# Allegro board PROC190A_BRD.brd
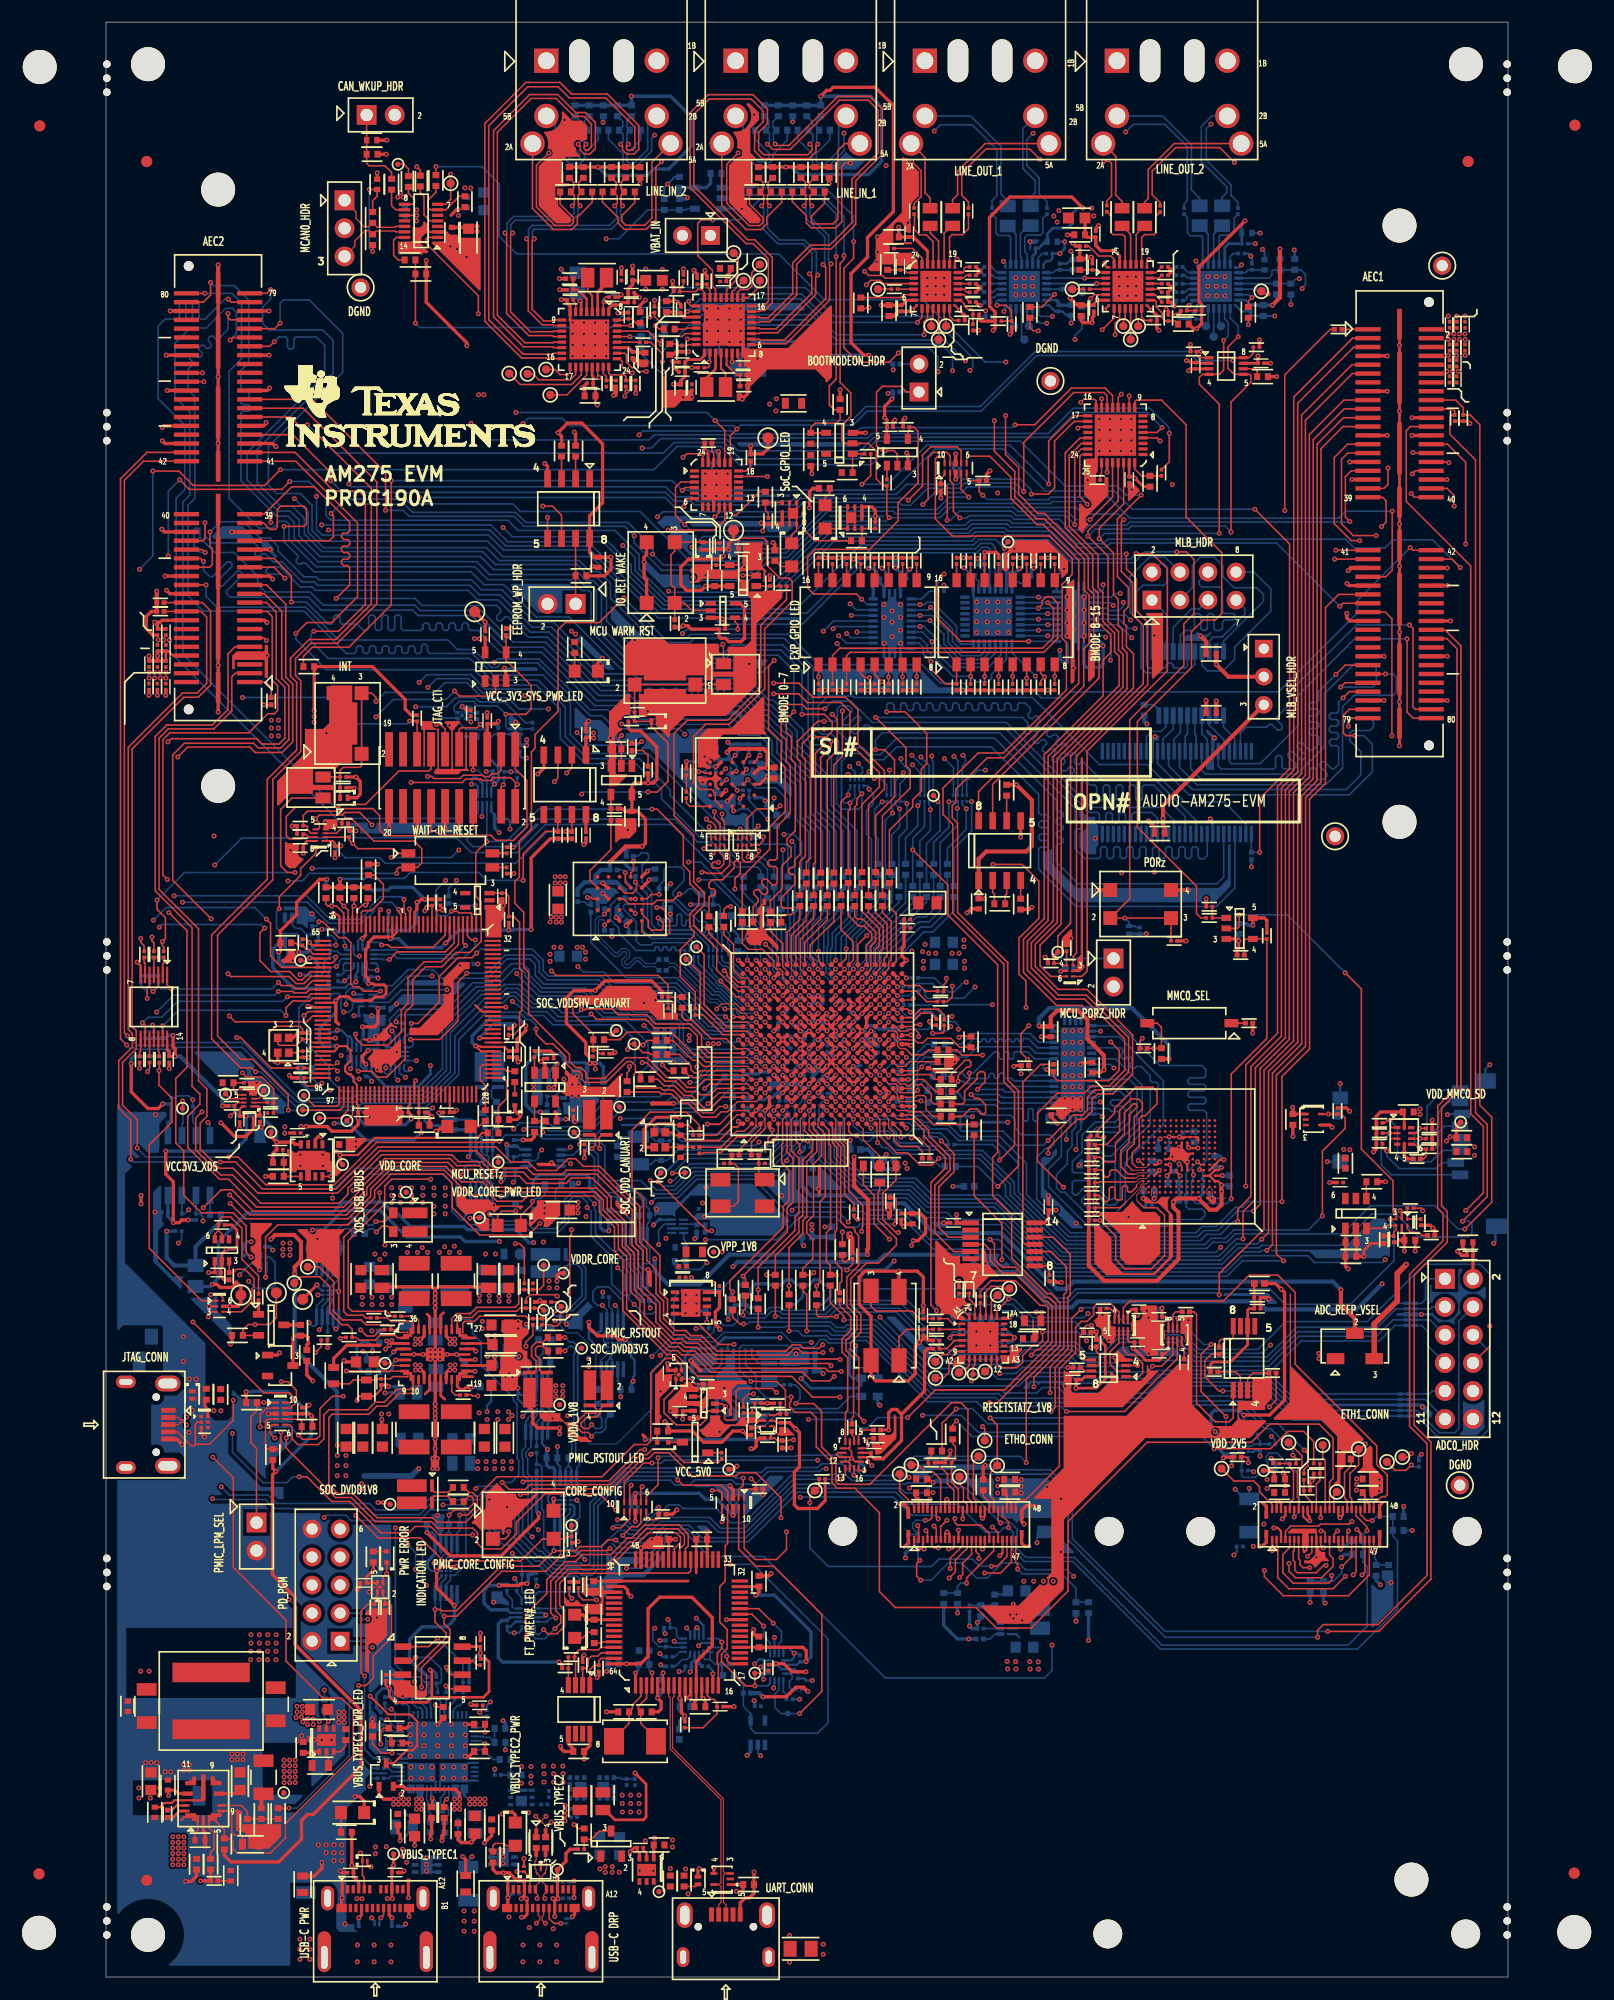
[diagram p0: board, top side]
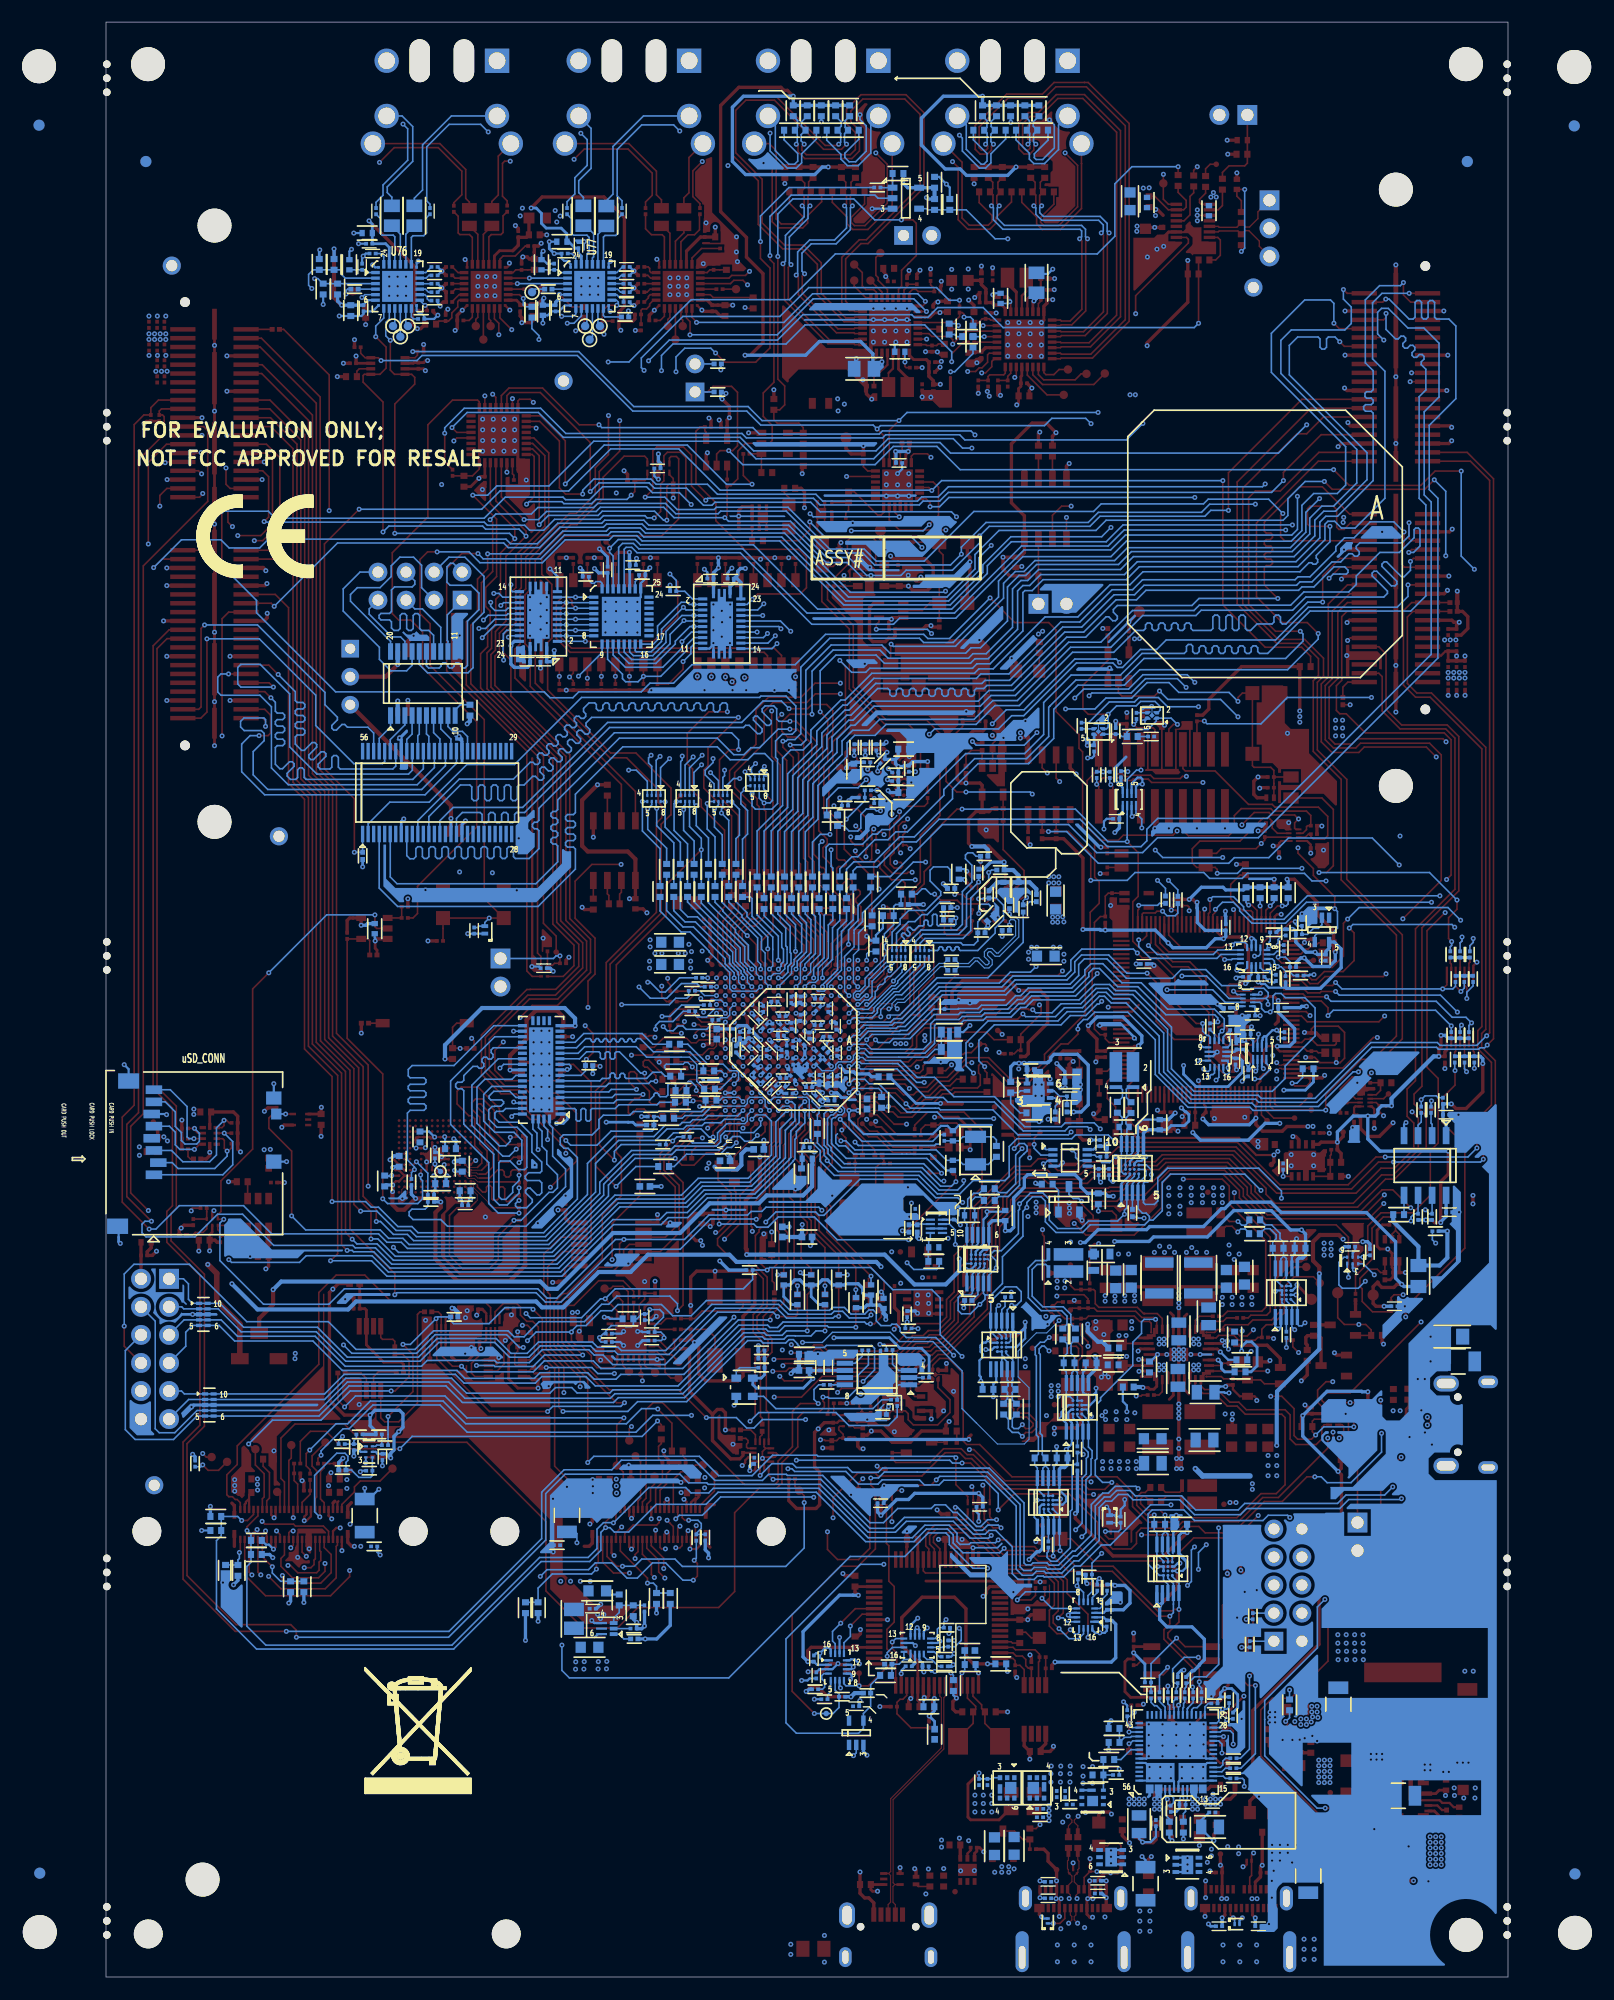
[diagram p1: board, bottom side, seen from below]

Outline 127 x 177 mm; copper layers: TOP, L02_GND1, L03_SIG1, L04_PWR1, L05_GND2, BOTTOM. Coordinates in mm from the lower left corner of the outline.
Outline path: 0,177 0,0 127,0 127,177 0,177

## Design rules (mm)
constraint set DEFAULT: min track width 0.147
net group AEC1_GPIO0_1: nets AEC1_GPIO0_1 N28268314
net group AUDIO_EXT_REFCLK0: nets AUDIO_EXT_REFCLK0 N29649892
net group AUDIO_EXT_REFCLK1: nets AUDIO_EXT_REFCLK1 AUDIO_EXT_REFCLK1__R
net group AUDIO_EXT_REFCLK2: nets AUDIO_EXT_REFCLK2 AUDIO_EXT_REFCLK2_R
net group CAN_DP1: nets MCAN0_CAN_H MCAN0_CAN_L
net group CDCE_CLKOUT_1: nets CDCE_CLKOUT_1 N27176072
net group CPSW_RGMII1_TD0: nets CPSW_RGMII1_TD0 N28084397
net group CPSW_RGMII1_TD1: nets CPSW_RGMII1_TD1 N28084399
net group CPSW_RGMII1_TD2: nets CPSW_RGMII1_TD2 N28084409
net group CPSW_RGMII1_TD3: nets CPSW_RGMII1_TD3 N28084411
net group CPSW_RGMII1_TXC: nets CPSW_RGMII1_TXC CPSW_RGMII_TXC_R
net group CPSW_RGMII2_TD0: nets CPSW_RGMII2_TD0 N28084427
net group CPSW_RGMII2_TD2: nets CPSW_RGMII2_TD2 N28084431
net group CPSW_RGMII2_TD3: nets CPSW_RGMII2_TD3 N28084433
net group CPSW_RGMII2_TXC: nets CPSW_RGMII2_TXC CPSW_RGMII2_TXC_R
net group DP1_USB_SOC: nets SOC_USB0_DM SOC_USB0_DP
net group DP_CONN2: nets USBC_CONN2_DM USBC_CONN2_DP
net group DP_XDS_USB: nets XDS_USB_DM XDS_USB_DP
net group DVDD3V3: nets DVDD3V3_N DVDD3V3_P
net group HYPERBUS0_CK: nets HYPERBUS0_CK N28088261
net group HYPERBUS0_CK#: nets HYPERBUS0_CK# N28088302
net group HYPERBUS0_CS#: nets HYPERBUS0_CS# N28088339
net group HYPERBUS0_DQ0: nets HYPERBUS0_DQ0 SOC_HYPERBUS0_DQ0
net group HYPERBUS0_DQ1: nets HYPERBUS0_DQ1 SOC_HYPERBUS0_DQ1
net group HYPERBUS0_DQ2: nets HYPERBUS0_DQ2 SOC_HYPERBUS0_DQ2
net group HYPERBUS0_DQ3: nets HYPERBUS0_DQ3 SOC_HYPERBUS0_DQ3
net group HYPERBUS0_DQ4: nets HYPERBUS0_DQ4 SOC_HYPERBUS0_DQ4
net group HYPERBUS0_DQ5: nets HYPERBUS0_DQ5 SOC_HYPERBUS0_DQ5
net group HYPERBUS0_DQ6: nets HYPERBUS0_DQ6 SOC_HYPERBUS0_DQ6
net group HYPERBUS0_DQ7: nets HYPERBUS0_DQ7 SOC_HYPERBUS0_DQ7
net group HYPERBUS0_RWDS: nets HYPERBUS0_RWDS N27995683
net group MCASP0_ACLKR: nets MCASP0_ACLKR MCASP0_ACLKR_R
net group MCASP0_ACLKX: nets MCASP0_ACLKX N29650058
net group MCASP0_AFSR: nets MCASP0_AFSR MCASP0_AFSR_R
net group MCASP0_AFSX: nets MCASP0_AFSX MCASP0_AFSX_R
net group MCASP0_AXR0: nets MCASP0_AXR0 MCASP0_AXR0_R
net group MCASP0_AXR1: nets MCASP0_AXR1 MCASP0_AXR1_R
net group MCASP0_AXR2: nets MCASP0_AXR2 MCASP0_AXR2_R
net group MCASP0_AXR3: nets MCASP0_AXR3 MCASP0_AXR3_R
net group MCASP0_AXR4: nets MCASP0_AXR4 MCASP0_AXR4_R
net group MCASP0_AXR5: nets MCASP0_AXR5 MCASP0_AXR5_R
net group MCASP0_AXR6_R: nets MCASP0_AXR6_R UART2_RXD_FET
net group MCASP0_AXR7: nets MCASP0_AXR7 MCASP0_AXR7_R
net group MCASP0_AXR8_R: nets MCASP0_AXR8_R OBSCLK0
net group MCASP0_AXR9: nets MCASP0_AXR9 MCASP0_AXR9_R
net group MCASP1_ACLKR_R: nets MCASP1_ACLKR_R PCM6240_MCASP1_ACLKR
net group MCASP1_ACLKX_R: nets MCASP1_ACLKX_R TAD5212_MCASP1_ACLKX
net group MCASP1_AFSR_R: nets MCASP1_AFSR_R PCM6240_MCASP1_AFSR
net group MCASP1_AFSX_R: nets MCASP1_AFSX_R TAD5212_MCASP1_AFSX
net group MCASP1_AXR0_R: nets MCASP1_AXR0_R PCM6240_MCASP1_AXR0
net group MCASP1_AXR2_R: nets MCASP1_AXR2_R PCM6240_MCASP1_AXR2
net group MCASP2_ACLKR: nets MCASP2_ACLKR MCASP2_ACLKR_R
net group MCASP2_ACLKX: nets MCASP2_ACLKX MCASP2_ACLKX_R
net group MCASP2_AFSR: nets MCASP2_AFSR MCASP2_AFSR_R
net group MCASP2_AFSX: nets MCASP2_AFSX MCASP2_AFSX_R
net group MCASP2_AXR0: nets MCASP2_AXR0 MCASP2_AXR0_R
net group MCASP2_AXR1: nets MCASP2_AXR1 MCASP2_AXR1_R
net group MCASP2_AXR2: nets MCASP2_AXR2 MCASP2_AXR2_R
net group MCASP2_AXR3: nets MCASP2_AXR3 MCASP2_AXR3_R
net group MCASP2_AXR4: nets MCASP2_AXR4 MCASP2_AXR4_R
net group MCASP2_AXR5: nets MCASP2_AXR5 MCASP2_AXR5_R
net group MCASP3_ACLKX: nets MCASP3_ACLKX N29649623
net group MCASP3_AFSX: nets MCASP3_AFSX N29649611
net group MCASP3_AXR0: nets MCASP3_AXR0 N29649563
net group MCASP3_AXR1: nets MCASP3_AXR1 N29649575
net group MCASP3_AXR2: nets MCASP3_AXR2 N29649587
net group MCASP3_AXR3: nets MCASP3_AXR3 N29649599
net group MCASP4_ACLKR_R: nets MCASP4_ACLKR_FET MCASP4_ACLKR_R
net group MCASP4_AFSR_R: nets MCASP4_AFSR_FET MCASP4_AFSR_R
net group MCASP4_AXR0_R: nets MCASP4_AXR0_FET MCASP4_AXR0_R
net group MCASP4_AXR3_R: nets MCASP4_AXR3_FET MCASP4_AXR3_R
net group MCASP4_AXR4_R: nets MCASP4_AXR4_FET MCASP4_AXR4_R
net group MCASP4_AXR5_R: nets MCASP4_AXR5_FET MCASP4_AXR5_R
net group OSC1_XI: nets N27975321 OSC1_XI
net group OSC1_XO: nets N27975317 OSC1_XO
net group OSPI_CLK: nets OSPI_CLK SOC_OSPI_CLK
net group OSPI_DQS: nets OSPI_DQS OSPI_DQS_SOC
net group PCMPCM1_IN1: nets PCM1_IN1N PCM1_IN1P
net group PCMPCM1_IN2: nets PCM1_IN2N PCM1_IN2P
net group PCMPCM1_IN3: nets PCM1_IN3N PCM1_IN3P
net group PCMPCM1_IN4: nets PCM1_IN4N PCM1_IN4P
net group PCMPCM2_IN1: nets PCM2_IN1N PCM2_IN1P
net group PCMPCM2_IN2: nets PCM2_IN2N PCM2_IN2P
net group PCMPCM2_IN3: nets PCM2_IN3N PCM2_IN3P
net group PCMPCM2_IN4: nets PCM2_IN4N PCM2_IN4P
net group RESET_STATZ: nets RESET_STATZ RESETSTATZ_1V8
net group SEC_REF_N: nets N27175817 SEC_REF_N
net group SEC_REF_P: nets N27175821 SEC_REF_P
net group SOC_DVDD1V8: nets SOC_DVDD1V8_N SOC_DVDD1V8_P
net group SOC_DVDD3V3: nets SOC_DVDD3V3_N SOC_DVDD3V3_P
net group SOC_MMC0_CLK: nets MMC0_CLK SOC_MMC0_CLK
net group SOC_MMC0_CMD_R: nets SOC_MMC0_CMD SOC_MMC0_CMD_R
net group SOC_MMC0_DAT0_R: nets SOC_MMC0_DAT0 SOC_MMC0_DAT0_R
net group SOC_MMC0_DAT1_R: nets SOC_MMC0_DAT1 SOC_MMC0_DAT1_R
net group SOC_MMC0_DAT2_R: nets SOC_MMC0_DAT2 SOC_MMC0_DAT2_R
net group SOC_MMC0_DAT3_R: nets SOC_MMC0_DAT3 SOC_MMC0_DAT3_R
net group SOC_MMC0_DAT4_R: nets SOC_MMC0_DAT4 SOC_MMC0_DAT4_R
net group SOC_MMC0_DAT5_R: nets SOC_MMC0_DAT5 SOC_MMC0_DAT5_R
net group SOC_MMC0_DAT6_R: nets SOC_MMC0_DAT6 SOC_MMC0_DAT6_R
net group SOC_MMC0_DAT7_R: nets SOC_MMC0_DAT7 SOC_MMC0_DAT7_R
net group SOC_OSPI_DQ0: nets OSPI_DQ0 SOC_OSPI_DQ0
net group SOC_OSPI_DQ1: nets OSPI_DQ1 SOC_OSPI_DQ1
net group SOC_OSPI_DQ2: nets OSPI_DQ2 SOC_OSPI_DQ2
net group SOC_OSPI_DQ3: nets OSPI_DQ3 SOC_OSPI_DQ3
net group SOC_OSPI_DQ4: nets OSPI_DQ4 SOC_OSPI_DQ4
net group SOC_OSPI_DQ5: nets OSPI_DQ5 SOC_OSPI_DQ5
net group SOC_OSPI_DQ6: nets OSPI_DQ6 SOC_OSPI_DQ6
net group SOC_OSPI_DQ7: nets OSPI_DQ7 SOC_OSPI_DQ7
net group SOC_VDD_CANUART: nets SOC_VDD_CANUART_N SOC_VDD_CANUART_P
net group SOC_VDDSHV_CANUART: nets SOC_VDDSHV_CANUART_N SOC_VDDSHV_CANUART_P
net group VDD_0V85: nets VDD_0V85_N VDD_0V85_P
net group VDD_1V8: nets VDD_1V8_N VDD_1V8_P
net group VDD_CANUART: nets VDD_CANUART_N VDD_CANUART_P
net group VDD_CORE: nets VDD_CORE_N VDD_CORE_P
net group VDDA_1V8: nets VDDA_1V8_N VDDA_1V8_P
net group VDDR_CORE: nets VDDR_CORE_N VDDR_CORE_P
net group VDDSHV_CANUART: nets VDDSHV_CANUART_N VDDSHV_CANUART_P
net group WKUP_LFOSCO_XO: nets N27972730 WKUP_LFOSCO_XO
net group CPSW_RGMII2_TD1: nets N28084429
net group EMMC_MG: nets EMMC_CLK EMMC_CMD EMMC_D0 EMMC_D1 EMMC_D2 EMMC_D3 EMMC_D4 EMMC_D5 EMMC_D6 EMMC_D7
net group MCASP1_AXR1_R: nets MCASP1_AXR1_R TAD5212_1_DIN TAD5212_2_DIN TAD5212_3_DIN TAD5212_4_DIN TAD5212_MCASP1_AXR1
net group MCASP3_ACLKR: nets MCASP3_ACLKR MCASP4_ACLKX_FET MCASP4_ACLKX_R
net group MCASP3_AFSR: nets MCASP3_AFSR MCASP4_AFSX_FET MCASP4_AFSX_R
net group OSPI0_CSN0: nets N29295413 N29295438 OSPI0_CSN0 OSPI_CS
net group PWR: nets LDO_3V3 N24307354 N24307356 SOC_DVDD3V3_FB1 SOC_VDD_CANUART SOC_VDDSHV5_SDIO SOC_VDDSHV_CANUART VCC1V8_SYS_N VCC_0V85 VCC_1V8_FT4232 VCC_3V3_AVDD VCC_3V3_FT4232 VCC_CORE VCC_CORE_N VDDA_1V8_FB3 VDDA_1V8_FB_OSC VDDA_ADC0 VDDR_CANUART VDDSHV_SDIO VPHY_3V3_FT4232 VPLL_3V3_FT4232 VPP_1V8
net group RGMII1_RD: nets CPSW_RGMII1_RD0 CPSW_RGMII1_RD1 CPSW_RGMII1_RD2 CPSW_RGMII1_RD3 CPSW_RGMII1_RX_DV CPSW_RGMII1_RXC
net group RGMII2_RD: nets CPSW_RGMII2_RD0 CPSW_RGMII2_RD1 CPSW_RGMII2_RD2 CPSW_RGMII2_RD3 CPSW_RGMII2_RX_DV CPSW_RGMII2_RXC
net group RGMII2_TD: nets CPSW_RGMII2_TX_EN
net group RGMII_TD: nets CPSW_RGMII1_TX_EN

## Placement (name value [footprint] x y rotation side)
C1  0.022uF  [CAP0402_0-75]  24.07 166.31 0 top
C2  0.1uF  [CAP0402_0-75]  48.36 163.39 270 top
C3  0.1uF  [CAP0402_0-75]  65.51 163.39 270 top
C11  22uF  [CAP0402_1]  41.63 161.63 0 top
C12  22uF  [CAP0402_1]  43.55 161.63 180 top
C13  22uF  [CAP0402_1]  45.47 161.63 0 top
C14  22uF  [CAP0402_1]  47.42 161.63 180 top
C15  22uF  [CAP0402_1]  58.77 161.63 0 top
C16  22uF  [CAP0402_1]  60.72 161.63 180 top
C17  22uF  [CAP0402_1]  62.66 161.63 0 top
C18  22uF  [CAP0402_1]  64.61 161.63 180 top
C20  1uF  [CAP0201_0-5]  90.66 160.11 270 top
C21  1uF  [CAP0201_0-5]  95.49 160.1 270 top
C22  1uF  [CAP0201_0-5]  73.2 159.88 270 top
C23  1uF  [CAP0201_0-5]  78.13 159.88 270 top
C24  47uF  [CAP0805_1-5]  74.65 159.34 270 top
C25  47uF  [CAP0805_1-5]  76.68 159.34 270 top
C26  47uF  [CAP0805_1-5]  92.05 159.34 270 top
C27  47uF  [CAP0805_1-5]  94.08 159.34 270 top
C28  0.1uF  [CAP0402_0-75]  112.76 65.24 0 top
C29  0.1uF  [CAP0201_0-5]  72.76 157.82 90 top
C30  0.1uF  [CAP0201_0-5]  89.65 157.79 90 top
C31  10uF  [CAP0402_0-75]  88.2 157.74 180 top
C32  10uF  [CAP0402_0-75]  71.32 157.55 180 top
C33  4.7uF  [CAP0402_0-75]  112.77 66.5 180 top
C35  1uF  [CAP0201_0-5]  88.48 156.72 180 top
C37  0.1uF  [CAP0402_0-75]  118.1 66.71 0 top
C38  1uF  [CAP0201_0-5]  71.09 156.5 180 top
C42  10uF  [CAP0402_0-75]  70.8 155.06 90 top
C43  10uF  [CAP0402_0-75]  88.2 155.06 90 top
C45  0.1uF  [CAP0201_0-5]  71.96 154.85 90 top
C46  0.1uF  [CAP0201_0-5]  89.35 154.85 90 top
C47  0.1uF  [CAP0201_0-5]  78.52 154.83 0 top
C48  0.1uF  [CAP0201_0-5]  95.92 154.83 0 top
C49  0.1uF  [CAP0402_0-75]  56.1 154.7 0 top
C50  0.1uF  [CAP0201_0-5]  78.52 154.07 0 top
C51  0.1uF  [CAP0201_0-5]  95.92 154.07 0 top
C52  2.2uF  [CAP0201_0-75]  47.7 153.95 90 top
C53  0.1uF  [CAP0201_0-5]  46.69 153.89 270 top
C54  2.2uF  [CAP0201_0-75]  41.98 153.77 180 top
C55  1uF  [CAP0201_0-5]  55.91 153.52 0 top
C56  0.1uF  [CAP0201_0-5]  78.52 153.31 0 top
C57  0.1uF  [CAP0201_0-5]  95.92 153.31 0 top
C60  0.1uF  [CAP0201_0-5]  42.04 152.76 0 top
C61  0.1uF  [CAP0201_0-5]  78.52 152.55 0 top
C62  0.1uF  [CAP0201_0-5]  95.92 152.55 0 top
C63  1uF  [CAP0201_0-5]  47.58 152.5 0 top
C64  0.1uF  [CAP0201_0-5]  45.85 152.11 0 top
C65  1uF  [CAP0201_0-5]  42.04 151.87 180 top
C66  1uF  [CAP0201_0-5]  78.52 151.66 0 top
C67  1uF  [CAP0201_0-5]  95.92 151.66 0 top
C68  0.1uF  [CAP0201_0-5]  47.58 151.61 0 top
C69  1uF  [CAP0201_0-5]  111.78 71.93 180 top
C70  220pF  [CAP0402_0-75]  114.66 72 0 top
C71  10uF  [CAP0402_0-75]  50.77 151.24 90 top
C72  0.1uF  [CAP0201_0-5]  72.08 151.09 270 top
C73  0.1uF  [CAP0201_0-5]  89.48 151.09 270 top
C74  0.1uF  [CAP0201_0-5]  52.07 150.95 90 top
C75  10uF  [CAP0402_0-75]  70.93 150.88 270 top
C76  10uF  [CAP0402_0-75]  88.33 150.88 270 top
C77  10uF  [CAP0402_0-75]  48.38 150.25 90 top
C78  0.1uF  [CAP0201_0-5]  47.33 150.42 90 top
C81  0.1uF  [CAP0201_0-5]  52.18 147.44 270 top
C82  10uF  [CAP0402_0-75]  51.06 147.38 270 top
C84  0.1uF  [CAP0201_0-5]  47.69 146.86 270 top
C85  10uF  [CAP0402_0-75]  48.83 146.58 270 top
C86  0.1uF  [CAP0201_0-5]  52.18 146.21 180 top
C87  1uF  [CAP0201_0-5]  57.71 145.95 0 top
C88  2.2uF  [CAP0402_0-75]  122.82 74.73 180 top
C89  0.1uF  [CAP0201_0-5]  53.91 145.71 180 top
C90  1uF  [CAP0201_0-5]  52.18 145.32 180 top
C92  0.1uF  [CAP0201_0-5]  57.71 145.06 180 top
C93  0.1uF  [CAP0402_0-75]  122.81 75.99 180 top
C95  1uF  [CAP0201_0-5]  43.85 144.3 180 top
C96  2.2uF  [CAP0201_0-75]  57.77 144.05 0 top
C97  0.1uF  [CAP0201_0-5]  53.07 143.93 90 top
C98  2.2uF  [CAP0201_0-75]  52.05 143.87 270 top
C99  0.1uF  [CAP0201_0-5]  104.63 146.11 0 top
C100  0.1uF  [CAP0402_0-75]  43.85 143.16 180 top
C101  0.1uF  [CAP0201_0-5]  98.71 145.89 90 top
C102  0.1uF  [CAP0402_0-75]  107.51 77.64 90 top
C103  0.1uF  [CAP0402_0-75]  117.96 78.32 180 top
C104  12pF  [CAP0201_0-5]  74.03 58.36 90 top
C105  12pF  [CAP0201_0-5]  74.04 59.89 90 top
C107  4700pF  [CAP0402_0-75]  24.56 162.31 90 top
C109  0.1uF  [CAP0402_0-75]  63.84 137.3 270 top
C121  10uF  [CAP0402_0-75]  83.55 57.8 0 top
C122  0.01uF  [CAP0201_0-5]  55.16 137.08 0 bottom
C126  0.01uF  [CAP0201_0-5]  92.68 135.56 90 top
C128  0.1uF  [CAP0201_0-5]  121.71 149.59 90 top
C129  0.1uF  [CAP0201_0-5]  122.37 149.59 90 top
C130  1uF  [CAP0201_0-5]  123.11 149.59 90 top
C133  0.1uF  [CAP0201_0-5]  121.7 147.53 270 top
C134  1uF  [CAP0201_0-5]  122.36 147.53 270 top
C135  1uF  [CAP0201_0-5]  123.1 147.53 270 top
C136  0.1uF  [CAP0201_0-5]  71.02 140.33 0 top
C137  0.1uF  [CAP0201_0-5]  121.7 146.1 90 top
C138  1uF  [CAP0201_0-5]  122.36 146.1 90 top
C140  0.1uF  [CAP0201_0-5]  43.47 112.51 90 top
C141  0.1uF  [CAP0201_0-5]  121.7 144.65 270 top
C142  1uF  [CAP0201_0-5]  122.36 144.65 270 top
C146  0.1uF  [CAP0402_0-75]  102.66 94.92 270 bottom
C147  0.1uF  [CAP0201_0-5]  43.47 103.38 270 top
C148  0.1uF  [CAP0402_0-75]  55.14 126.42 90 top
C149  4.7uF  [CAP0402_0-75]  60.53 109.02 90 top
C150  0.1uF  [CAP0201_0-5]  93.57 60.45 180 top
C151  0.1uF  [CAP0201_0-5]  93.45 57.48 180 top
C160  1uF  [CAP0201_0-5]  4.66 121.77 90 top
C161  0.1uF  [CAP0201_0-5]  5.42 121.77 90 top
C164  0.1uF  [CAP0201_0-5]  76.77 68.28 180 top
C165  0.1uF  [CAP0201_0-5]  85.37 69.72 270 top
C167  1uF  [CAP0201_0-5]  4.66 120.32 270 top
C168  0.1uF  [CAP0201_0-5]  5.42 120.32 270 top
C169  0.1uF  [CAP0201_0-5]  34.53 113.75 90 top
C170  1uF  [CAP0201_0-5]  3.9 118.89 90 top
C171  1uF  [CAP0201_0-5]  4.66 118.89 90 top
C172  0.1uF  [CAP0201_0-5]  5.42 118.89 90 top
C174  1uF  [CAP0201_0-5]  3.89 116.83 270 top
C175  0.1uF  [CAP0201_0-5]  4.65 116.83 270 top
C176  0.1uF  [CAP0201_0-5]  5.42 116.83 270 top
C182  100pF  [CAP0201_0-5]  67.64 65.29 270 top
C188  100pF  [CAP0201_0-5]  77.65 77.9 180 bottom
C190  0.01uF  [CAP0201_0-5]  35.87 97.85 270 top
C192  0.1uF  [CAP0201_0-5]  5.72 83.08 270 top
C197  1uF  [CAP0201_0-5]  40.27 83.16 180 top
C201  10uF  [CAP0402_1]  35.76 55.42 0 bottom
C202  10uF  [CAP0402_0-75]  73.04 68.65 270 top
C203  0.1uF  [CAP0201_0-5]  17.8 93.68 270 top
C205  18pF  [CAP0402_0-75]  52.05 76.68 90 top
C207  1uF  [CAP0201_0-5]  42.34 78.21 270 top
C208  0.01uF  [CAP0201_0-5]  32.99 91.72 180 bottom
C209  18pF  [CAP0402_0-75]  52.05 74.67 90 top
C213  18pF  [CAP0402_0-75]  50.29 76.16 270 bottom
C215  0.1uF  [CAP0201_0-5]  36.48 85.59 270 top
C216  18pF  [CAP0402_0-75]  50.29 73.48 90 bottom
C217  12pF  [CAP0201_0-5]  17.81 85.2 270 top
C221  0.01uF  [CAP0201_0-5]  36.48 83.56 270 top
C222  1uF  [CAP0201_0-5]  37.24 83.56 270 top
C223  12pF  [CAP0201_0-5]  17.81 83.54 90 top
C224  1uF  [CAP0201_0-5]  61.57 81.23 270 bottom
C225  0.1uF  [CAP0201_0-5]  17.65 81.41 0 top
C226  22uF  [CAP0603_1]  23.08 63.2 270 top
C227  47uF  [CAP0805_1-5]  24.99 63.2 270 top
C228  47uF  [CAP0805_1-5]  34.65 63.2 270 top
C229  22uF  [CAP0603_1]  36.48 63.2 270 top
C231  0.1uF  [CAP0201_0-5]  23.12 78.29 180 top
C232  0.01uF  [CAP0201_0-5]  27.11 78.29 180 top
C233  1uF  [CAP0201_0-5]  28.61 78.29 0 top
C234  0.01uF  [CAP0201_0-5]  30.85 78.29 180 top
C235  0.1uF  [CAP0201_0-5]  12.12 77.67 90 top
C236  0.1uF  [CAP0201_0-5]  13.94 77.72 90 top
C240  2.2uF  [CAP0402_0-75]  28.82 77.12 0 top
C241  1uF  [CAP0201_0-5]  17.34 76.42 180 top
C242  2.2uF  [CAP0603_1]  35.72 59.03 0 top
C243  15pF  [CAP0201_0-5]  15.74 74.9 0 top
C244  2.2uF  [CAP0402_0-75]  21.62 75.38 0 top
C245  100pF  [CAP0201_0-5]  50.92 87.42 270 top
C246  2.2uF  [CAP0603_1]  35.72 55.37 0 top
C247  2.2uF  [CAP0201_0-75]  52.24 64.34 180 top
C248  100pF  [CAP0201_0-5]  45.31 83.6 0 top
C249  2.2uF  [CAP0603_1]  23.46 55.69 180 top
C250  4.7uF  [CAP0402_0-75]  9.08 52.76 90 top
C251  0.1uF  [CAP0201_0-5]  52.22 63.35 180 top
C254  2.2uF  [CAP0603_1]  35.72 53.57 0 top
C255  1uF  [CAP0201_0-5]  55.57 62.28 90 top
C256  2.2uF  [CAP0603_1]  23.26 48.82 90 top
C257  22uF  [CAP0603_1]  25.04 48.82 90 top
C258  22uF  [CAP0603_1]  34.27 48.82 90 top
C259  2.2uF  [CAP0603_1]  32.18 48.74 180 bottom
C260  0.1uF  [CAP0603_1]  36.14 48.81 90 top
C261  0.1uF  [CAP0603_1]  21.75 48.82 90 top
C262  0.1uF  [CAP0402_0-75]  42.83 20.42 0 top
C263  4.7uF  [CAP0402_0-75]  44.17 35.34 270 top
C264  0.1uF  [CAP0402_0-75]  44.23 32.84 270 top
C265  1uF  [CAP0201_0-5]  67.63 56.74 0 bottom
C266  0.1uF  [CAP0201_0-5]  67.63 55.98 180 bottom
C267  0.1uF  [CAP0402_0-75]  10.39 52.74 90 top
C269  18pF  [CAP0402_0-75]  46.89 24 180 top
C270  18pF  [CAP0402_0-75]  48.94 24 0 top
C271  10uF  [CAP0402_0-75]  114.31 45.09 0 top
C272  10uF  [CAP0402_0-75]  73.88 45.09 0 top
C273  10uF  [CAP0402_0-75]  106.31 45.09 0 top
C274  10uF  [CAP0402_0-75]  81.86 45.06 0 top
C275  0.1uF  [CAP0402_0-75]  50.48 39.63 0 top
C276  0.1uF  [CAP0402_0-75]  106.31 43.88 0 top
C277  0.1uF  [CAP0402_0-75]  114.32 43.87 0 top
C278  0.1uF  [CAP0402_0-75]  73.88 43.84 0 top
C279  0.1uF  [CAP0402_0-75]  81.88 43.9 0 top
C280  0.1uF  [CAP0402_0-75]  53.8 24.47 180 top
C281  0.1uF  [CAP0402_0-75]  53.96 39.63 180 top
C282  0.1uF  [CAP0201_0-5]  55.63 24.48 180 top
C283  0.01uF  [CAP0201_0-5]  48.4 11.71 0 top
C284  0.1uF  [CAP0201_0-5]  61.57 55.2 270 bottom
C285  2.2uF  [CAP0402_0-75]  50.11 11.95 0 top
C286  1uF  [CAP0201_0-5]  62.33 55.2 270 bottom
C287  10uF  [CAP0402_0-75]  51.12 8.69 270 top
C288  0.1uF  [CAP0402_0-75]  59.15 30.34 270 top
C289  0.1uF  [CAP0402_0-75]  59.15 35.84 270 top
C290  10uF  [CAP0402_0-75]  63.74 56.38 180 bottom
C291  0.1uF  [CAP0402_0-75]  52.37 8.69 270 top
C292  0.1uF  [CAP0201_0-5]  33.91 30.19 90 top
C293  0.1uF  [CAP0201_0-5]  61.12 49.91 270 top
C295  0.1uF  [CAP0402_0-75]  58.21 8.37 0 top
C300  0.01uF  [CAP0201_0-5]  23.3 35.68 0 top
C301  0.01uF  [CAP0201_0-5]  33.85 24.6 180 top
C302  10uF  [CAP0603_1]  19.29 24.21 0 top
C303  4.7uF  [CAP0402_0-75]  30.54 23.95 270 top
C305  220pF  [CAP0402_0-75]  33.84 22.88 180 top
C306  220pF  [CAP0402_0-75]  26.1 22.53 0 top
C307  220pF  [CAP0402_0-75]  24.14 22.28 90 top
C308  330pF  [CAP0402_0-75]  21.71 21.94 90 top
C309  4.7uF  [CAP0402_0-75]  26.37 21.18 0 top
C310  1uF  [CAP0402_0-75]  17.86 20.79 90 top
C312  220pF  [CAP0402_0-75]  33.84 20.42 180 top
C317  47uF  [CAP0805_1-5]  42.93 15.92 270 top
C318  47uF  [CAP0805_1-5]  45.01 15.91 270 top
C319  10uF  [CAP0402_0-75]  29.48 14.9 90 top
C320  10uF  [CAP0402_0-75]  30.63 14.9 90 top
C321  0.1uF  [CAP0402_0-75]  26.43 14.26 270 top
C322  10uF  [CAP0603_1]  33.42 13.78 270 top
C323  0.1uF  [CAP0402_0-75]  34.94 13.78 270 top
C324  10uF  [CAP0603_1]  27.96 13.54 270 top
C325  0.1uF  [CAP0402_0-75]  31.89 13.43 270 top
C326  0.01uF  [CAP0201_0-5]  26.17 9.46 0 top
C327  0.01uF  [CAP0201_0-5]  22.14 9.45 180 top
C329  0.1uF  [CAP0402_0-75]  62.2 168.97 270 bottom
C330  0.1uF  [CAP0402_0-75]  45.06 168.97 270 bottom
C331  22uF  [CAP0402_1]  65.09 167.21 180 bottom
C332  22uF  [CAP0402_1]  63.14 167.21 0 bottom
C333  22uF  [CAP0402_1]  61.22 167.21 180 bottom
C334  22uF  [CAP0402_1]  59.3 167.21 0 bottom
C335  22uF  [CAP0402_1]  47.94 167.21 180 bottom
C336  22uF  [CAP0402_1]  46 167.21 0 bottom
C337  22uF  [CAP0402_1]  44.08 167.21 180 bottom
C338  22uF  [CAP0402_1]  42.16 167.21 0 bottom
C340  0.1uF  [CAP0402_0-75]  51.94 162.5 90 bottom
C341  1uF  [CAP0201_0-5]  102.54 159.88 270 bottom
C342  1uF  [CAP0201_0-5]  97.65 159.88 270 bottom
C343  1uF  [CAP0201_0-5]  85.24 159.88 270 bottom
C344  1uF  [CAP0201_0-5]  80.26 159.88 270 bottom
C345  47uF  [CAP0805_1-5#2]  101.1 159.47 270 bottom
C346  47uF  [CAP0805_1-5#2]  99.07 159.47 270 bottom
C347  47uF  [CAP0805_1-5#2]  83.76 159.47 270 bottom
C348  47uF  [CAP0805_1-5#2]  81.68 159.44 270 bottom
C349  10uF  [CAP0402_0-75]  103.34 157.9 0 bottom
C350  10uF  [CAP0402_0-75]  85.7 157.12 0 bottom
C351  0.1uF  [CAP0201_0-5]  103.16 156.93 0 bottom
C352  0.1uF  [CAP0201_0-5]  84.2 156.8 90 bottom
C353  1uF  [CAP0201_0-5]  102.85 156.04 0 bottom
C354  1uF  [CAP0201_0-5]  85.45 156.04 0 bottom
C355  10uF  [CAP0402_0-75]  104.95 155.03 90 bottom
C356  10uF  [CAP0402_0-75]  87.55 155.03 90 bottom
C357  0.1uF  [CAP0201_0-5]  103.8 154.85 90 bottom
C358  0.1uF  [CAP0201_0-5]  86.4 154.85 90 bottom
C359  0.1uF  [CAP0201_0-5]  97.24 154.83 180 bottom
C360  0.1uF  [CAP0201_0-5]  79.84 154.83 180 bottom
C361  0.1uF  [CAP0201_0-5]  97.24 154.07 180 bottom
C362  0.1uF  [CAP0201_0-5]  79.84 154.07 180 bottom
C363  1uF  [CAP0805_1-5#2]  42.71 153.4 90 bottom
C364  0.1uF  [CAP0201_0-5]  97.24 153.31 180 bottom
C365  0.1uF  [CAP0201_0-5]  79.84 153.31 180 bottom
C366  0.1uF  [CAP0201_0-5]  97.24 152.55 180 bottom
C367  0.1uF  [CAP0201_0-5]  79.84 152.55 180 bottom
C368  10uF  [CAP0402_0-75]  45.96 151.99 90 bottom
C369  1uF  [CAP0201_0-5]  97.24 151.78 180 bottom
C370  1uF  [CAP0201_0-5]  79.84 151.66 180 bottom
C371  0.1uF  [CAP0201_0-5]  103.67 151.09 270 bottom
C372  0.1uF  [CAP0201_0-5]  86.27 151.09 270 bottom
C373  10uF  [CAP0402_0-75]  104.82 150.88 270 bottom
C374  10uF  [CAP0402_0-75]  87.43 150.91 270 bottom
C378  10uF  [CAP0402_0-75]  55.09 147.15 0 bottom
C379  1uF  [CAP0805_1-5#2]  58.33 145.61 0 bottom
C382  0.1uF  [CAP0201_0-5]  77.58 58.39 0 bottom
C383  0.1uF  [CAP0201_0-5]  77.58 57.63 0 bottom
C384  0.1uF  [CAP0201_0-5]  78.21 59.75 270 bottom
C385  10uF  [CAP0402_0-75]  79.72 59.59 0 bottom
C386  0.1uF  [CAP0201_0-5]  81.46 58.25 180 bottom
C387  0.1uF  [CAP0201_0-5]  81.46 57.49 180 bottom
C388  0.1uF  [CAP0402_0-75]  54.75 111.17 180 bottom
C389  0.1uF  [CAP0402_0-75]  59.26 109.36 270 bottom
C390  0.1uF  [CAP0402_0-75]  54.74 107.24 180 bottom
C391  0.1uF  [CAP0201_0-5]  79.28 127.84 0 bottom
C393  0.1uF  [CAP0201_0-5]  81.56 127.41 270 bottom
C394  0.1uF  [CAP0201_0-5]  72.25 126.61 180 bottom
C395  0.1uF  [CAP0201_0-5]  70.41 126.61 0 bottom
C408  0.1uF  [CAP0201_0-5]  88.86 119.09 0 bottom
C409  0.1uF  [CAP0201_0-5]  87.36 119.09 180 bottom
C414  0.1uF  [CAP0201_0-5]  14.12 66.12 180 bottom
C415  0.01uF  [CAP0201_0-5]  33.05 114.43 270 top
C416  0.01uF  [CAP0201_0-5]  37.49 111.24 90 bottom
C417  8.2pF  [CAP0201_0-5]  32.33 112.31 180 bottom
C421  0.1uF  [CAP0201_0-5]  87.35 91.34 180 bottom
C427  0.1uF  [CAP0402_0-75]  47.11 53.21 180 bottom
C428  0.1uF  [CAP0402_0-75]  45.11 53.21 0 bottom
C429  1uF  [CAP0201_0-5]  66.53 80.5 315 bottom
C430  0.1uF  [CAP0201_0-5]  25.57 95.04 270 bottom
C432  1uF  [CAP0201_0-5]  62.5 88.58 180 bottom
C434  1uF  [CAP0201_0-5]  61.57 87.67 90 bottom
C437  1uF  [CAP0201_0-5]  63.31 80.57 180 bottom
C440  1uF  [CAP0201_0-5]  60.86 86.06 270 bottom
C441  0.22uF  [CAP0201_0-5]  63.32 82.87 315 bottom
C443  1uF  [CAP0201_0-5]  68.13 82.76 315 bottom
C445  0.22uF  [CAP0201_0-5]  68.11 81.23 225 bottom
C446  1uF  [CAP0201_0-5]  69.57 85.29 270 bottom
C447  0.1uF  [CAP0201_0-5]  62.53 86.17 180 bottom
C448  0.22uF  [CAP0201_0-5]  62.5 87.66 135 bottom
C449  22pF  [CAP0201_0-5]  62.49 82.82 315 bottom
C451  1uF  [CAP0201_0-5]  62.52 79.6 225 bottom
C453  1uF  [CAP0201_0-5]  64.1 88.49 90 bottom
C454  1uF  [CAP0201_0-5]  65.65 81.39 180 bottom
C455  0.1uF  [CAP0201_0-5]  16.5 92.3 90 bottom
C460  0.22uF  [CAP0201_0-5]  65.73 86.07 225 bottom
C461  1uF  [CAP0201_0-5]  64.92 88.47 90 bottom
C462  0.22uF  [CAP0201_0-5]  63.31 85.23 90 bottom
C463  1uF  [CAP0201_0-5]  66.62 86.03 90 bottom
C465  0.1uF  [CAP0201_0-5]  68.12 86.87 45 bottom
C466  0.1uF  [CAP0201_0-5]  64.75 84.46 90 bottom
C467  1uF  [CAP0201_0-5]  67.32 86.09 135 bottom
C468  0.22uF  [CAP0201_0-5]  64.9 86.12 270 bottom
C469  0.1uF  [CAP0201_0-5]  23.72 90.55 180 bottom
C470  0.1uF  [CAP0201_0-5]  22.35 90.55 0 bottom
C471  1uF  [CAP0201_0-5]  68.76 85.29 270 bottom
C473  0.1uF  [CAP0201_0-5]  5.33 69.25 0 bottom
C477  0.22uF  [CAP0201_0-5]  68.12 82.09 135 bottom
C478  0.1uF  [CAP0201_0-5]  36.94 75.5 270 bottom
C483  1uF  [CAP0201_0-5]  72.03 68.86 270 top
C484  1uF  [CAP0201_0-5]  60.77 83.68 90 bottom
C485  1uF  [CAP0201_0-5]  63.97 84.61 45 bottom
C488  1uF  [CAP0201_0-5]  20.54 87.76 180 bottom
C489  0.1uF  [CAP0201_0-5]  21.49 108.65 180 top
C490  0.1uF  [CAP0201_0-5]  66.46 88.32 180 bottom
C493  0.1uF  [CAP0201_0-5]  67.16 83.66 270 bottom
C494  0.22uF  [CAP0201_0-5]  65.72 86.98 0 bottom
C495  1uF  [CAP0201_0-5]  72.57 95.76 180 top
C497  4.7uF  [CAP0201_0-5]  72.57 95 180 top
C498  0.1uF  [CAP0402_0-75]  98.56 76.06 90 bottom
C500  0.1uF  [CAP0201_0-5]  25.47 87.76 180 bottom
C501  1uF  [CAP0201_0-5]  64.1 82.86 315 bottom
C502  1uF  [CAP0201_0-5]  61.84 83.88 45 bottom
C503  0.1uF  [CAP0402_0-75]  100.45 73.85 90 bottom
C504  2.2uF  [CAP0402_0-75]  95.79 75 0 bottom
C505  0.1uF  [CAP0201_0-5]  67.31 82.04 315 bottom
C506  1uF  [CAP0201_0-5]  65.65 80.41 315 bottom
C508  1uF  [CAP0201_0-5]  61.29 79.35 0 bottom
C509  1uF  [CAP0201_0-5]  60.79 81.26 270 bottom
C511  0.1uF  [CAP0201_0-5]  23.18 87.04 180 bottom
C512  1uF  [CAP0201_0-5]  61.7 82.84 45 bottom
C514  0.1uF  [CAP0402_0-75]  94.73 73.41 270 bottom
C515  0.1uF  [CAP0201_0-5]  23.59 85.35 180 bottom
C516  0.1uF  [CAP0201_0-5]  20.24 85.27 270 bottom
C517  1uF  [CAP0201_0-5]  62.38 80.46 90 bottom
C518  2.2uF  [CAP0402_0-75]  101.75 72.07 90 bottom
C520  0.1uF  [CAP0402_0-75]  96.69 71.83 0 bottom
C521  0.1uF  [CAP0402_0-75]  94.47 71.19 180 bottom
C524  0.1uF  [CAP0402_0-75]  20.83 65.98 180 bottom
C525  0.1uF  [CAP0402_0-75]  18.83 65.98 0 bottom
C527  1uF  [CAP0201_0-5]  94.46 69.86 180 bottom
C528  0.1uF  [CAP0201_0-5]  23.54 81.82 90 bottom
C529  0.1uF  [CAP0201_0-5]  5.61 78.07 0 bottom
C532  0.1uF  [CAP0603_1]  23.88 63.5 270 bottom
C533  100uF  [CAP1210_2-75]  31.58 63.29 270 bottom
C534  100uF  [CAP1210_2-75]  28.05 63.29 270 bottom
C535  2.2uF  [CAP0603_1]  34.12 63.21 270 bottom
C536  2.2uF  [CAP0603_1]  25.51 63.21 270 bottom
C537  0.1uF  [CAP0603_1]  35.53 63.16 270 bottom
C538  0.1uF  [CAP0201_0-5]  10.29 60.73 180 bottom
C546  10uF  [CAP0805_1-5]  27.12 59.82 90 bottom
C547  10uF  [CAP0805_1-5]  29.82 58.45 270 bottom
C555  0.47uF  [CAP0402_0-75]  34.4 53.42 0 bottom
C559  0.1uF  [CAP0402_0-75]  39.76 55.6 180 bottom
C560  0.1uF  [CAP0402_0-75]  37.76 55.6 0 bottom
C561  4.7uF  [CAP0402_0-75]  32.47 55.23 90 bottom
C565  10uF  [CAP0805_1-5]  29.9 54.25 90 bottom
C572  10uF  [CAP0805_1-5]  27.39 52.94 180 bottom
C574  0.1uF  [CAP0201_0-5]  36.35 33.53 270 bottom
C575  0.1uF  [CAP0201_0-5]  36.35 32 90 bottom
C576  0.47uF  [CAP0402_0-75]  24.77 57.94 90 bottom
C592  47uF  [CAP0805_1-5]  32.17 46.51 180 bottom
C593  47uF  [CAP0805_1-5]  27.49 48.62 0 bottom
C597  0.1uF  [CAP0402_0-75]  42.39 46.99 180 bottom
C598  0.1uF  [CAP0402_0-75]  40.39 46.99 0 bottom
C599  0.1uF  [CAP0402_0-75]  45.95 28.35 0 bottom
C602  0.1uF  [CAP0201_0-5]  101.96 47.09 270 bottom
C603  0.1uF  [CAP0402_0-75]  31.56 40.98 180 bottom
C604  0.1uF  [CAP0402_0-75]  29.56 40.98 0 bottom
C605  1000pF  [CAP1206_1-75]  4.51 55.74 180 bottom
C606  0.1uF  [CAP0402_0-75]  48.72 28.29 0 bottom
C607  0.1uF  [CAP0402_0-75]  52.46 24.47 180 bottom
C608  0.1uF  [CAP0201_0-5]  52.76 28.14 0 bottom
C609  0.1uF  [CAP0201_0-5]  48.16 114.54 180 top
C610  1000pF  [CAP1206_1-75]  85.24 41.8 90 bottom
C611  1000pF  [CAP1206_1-75]  103.56 41.78 90 bottom
C612  0.1uF  [CAP0201_0-5]  54.28 28.14 180 bottom
C613  0.1uF  [CAP0201_0-5]  35.09 41.41 270 bottom
C614  22uF  [CAP0603_1]  82.49 34.96 180 bottom
C615  120pF  [CAP0201_0-5]  78.22 33.37 90 bottom
C616  0.1uF  [CAP0201_0-5]  82.91 33.35 180 bottom
C617  0.1uF  [CAP0201_0-5]  62.66 27.31 90 bottom
C618  0.1uF  [CAP0201_0-5]  62.87 28.83 270 bottom
C620  4.7uF  [CAP0603_1]  83.2 29.85 0 bottom
C622  0.1uF  [CAP0201_0-5]  93.65 94.74 90 bottom
C631  4.7uF  [CAP0402_0-75]  35.68 21.24 0 bottom
C638  0.1uF  [CAP0201_0-5]  47.16 17.65 90 bottom
C639  0.1uF  [CAP0201_0-5]  40.88 16.56 270 bottom
C640  1uF  [CAP0201_0-5]  42.38 15.23 180 bottom
C641  0.01uF  [CAP0201_0-5]  26.78 14.9 0 bottom
C642  0.01uF  [CAP0201_0-5]  31.9 13.93 270 bottom
C643  4.7uF  [CAP0805_1-5]  26.99 13.58 0 bottom
C644  4.7uF  [CAP0805_1-5]  33.42 13.83 270 bottom
C646  10uF  [CAP0603_1]  44.74 11.87 270 bottom
C647  10uF  [CAP0603_1]  46.52 11.84 270 bottom
C648  1000pF  [CAP1206_1-75]  18.1 9.13 90 bottom
C649  0.01uF  [CAP0201_0-5]  37.16 8.72 180 bottom
C650  0.01uF  [CAP0201_0-5]  41.67 8.61 0 bottom
C651  1000pF  [CAP1206_1-75]  32.83 8.45 90 bottom
C652  0.01uF  [CAP0201_0-5]  37.15 7.56 180 bottom
C653  0.01uF  [CAP0201_0-5]  41.66 7.12 0 bottom
C654  0.01uF  [CAP0201_0-5]  26.17 4.59 0 bottom
C655  0.01uF  [CAP0201_0-5]  22.61 4.59 180 bottom
C657  0.22uF  [CAP0201_0-5]  64.09 86.85 90 bottom
C658  0.22uF  [CAP0201_0-5]  65.34 84.05 90 bottom
C659  0.22uF  [CAP0201_0-5]  62.5 83.64 225 bottom
C660  1uF  [CAP0201_0-5]  64.91 82.18 180 bottom
C662  1uF  [CAP0201_0-5]  67.46 87.65 90 bottom
C663  1uF  [CAP0201_0-5]  65.88 85.24 180 bottom
C787  0.1uF  [CAP0402_0-75]  89.33 82.35 90 top
C3494  0.1uF  [CAP0402_0-75]  4.42 14.91 90 top
C3497  0.1uF  [CAP0402_0-75]  1.98 24.51 270 top
C3625  10uF  [CAP1206_2]  14.27 18.08 90 top
C3627  10uF  [CAP0402_0-75]  8.51 12.38 180 top
C3628  10uF  [CAP1206_2]  9.93 16.41 0 bottom
C3629  0.22uF  [CAP0603_1]  12.14 17.73 90 top
C3630  0.22uF  [CAP0603_1]  4.06 17.73 90 top
C3631  0.1uF  [CAP0402_0-75]  5.61 17.37 90 top
C3636  47uF  [CAP1206_2]  3.68 24.54 270 top
C3637  47uF  [CAP1206_2]  15.37 24.69 270 top
C3638  47uF  [CAP1206_2]  15.37 24.69 270 bottom
C3639  33pF  [CAP0402_0-75]  11.3 9.16 90 top
C3642  0.01uF  [CAP0201_0-5]  39.67 79.74 180 bottom
C3643  1uF  [CAP0402_0-75]  39.69 81.07 180 bottom
C3644  2.2uF  [CAP0201_0-75]  43.23 82.16 0 bottom
C3645  1uF  [CAP0201_0-5]  69.93 83.99 90 bottom
C3647  1uF  [CAP0201_0-5]  63.45 81.87 45 bottom
C3649  1uF  [CAP0201_0-5]  68.12 84.44 45 bottom
C3652  1uF  [CAP0201_0-5]  64.78 81.4 45 bottom
C3653  1uF  [CAP0201_0-5]  60 81.66 270 bottom
C3655  1uF  [CAP0201_0-5]  68.9 84.43 45 bottom
C3656  1uF  [CAP0201_0-5]  65.08 80 0 bottom
C3657  12pF  [CAP0201_0-5]  59.41 73.66 180 top
C3658  12pF  [CAP0201_0-5]  56.26 73.66 180 top
C3659  0.1uF  [CAP0402_0-75]  85.57 85.6 270 top
C3660  0.1uF  [CAP0402_0-75]  86.08 78 0 top
C3661  1uF  [CAP0201_0-5]  67.3 81.24 315 bottom
C3692  0.1uF  [CAP0402_0-75]  31.33 157.95 90 top
C3694  0.1uF  [CAP0402_0-75]  32.7 160.67 90 bottom
C3695  4.7uF  [CAP0603_1]  32.84 157.49 90 top
C3696  4.7uF  [CAP0603_1]  34.24 160.78 90 bottom
C3697  0.1uF  [CAP0402_0-75]  27.09 159.92 270 bottom
C3698  0.1uF  [CAP0402_0-75]  95.45 103.53 180 top
C3701  0.1uF  [CAP0402_0-75]  100.11 114.47 180 top
C3702  0.1uF  [CAP0402_0-75]  100.11 119.78 180 top
C3703  0.1uF  [CAP0201_0-5]  77.05 136.59 0 bottom
C3704  0.1uF  [CAP0201_0-5]  87.6 54.09 0 top
C3705  0.1uF  [CAP0402_0-75]  47.64 105.07 270 top
C3706  4.7uF  [CAP0402_0-75]  45.71 98.66 90 bottom
C3707  0.1uF  [CAP0402_0-75]  46.83 95.91 135 bottom
C3708  0.1uF  [CAP0402_0-75]  49.75 99.85 90 bottom
C3709  0.1uF  [CAP0402_0-75]  44.34 98.66 270 bottom
C3710  330pF  [CAP0402_0-75]  57.7 62.2 270 bottom
C3711  330pF  [CAP0402_0-75]  60.63 63.12 270 bottom
C3712  330pF  [CAP0402_0-75]  64.36 61.34 270 bottom
C3713  330pF  [CAP0402_0-75]  65.61 63.12 270 bottom
C3714  330pF  [CAP0402_0-75]  56.57 60.98 270 bottom
C3715  330pF  [CAP0402_0-75]  59.05 61.06 270 bottom
C3716  330pF  [CAP0402_0-75]  63.12 63.12 270 bottom
C3717  330pF  [CAP0402_0-75]  61.87 61.34 270 bottom
C3718  0.1uF  [CAP0201_0-5]  47.86 42.57 0 bottom
C3719  0.1uF  [CAP0201_0-5]  56.83 42.9 180 bottom
C3720  0.1uF  [CAP0201_0-5]  68.28 46.74 90 bottom
C3721  0.1uF  [CAP0201_0-5]  69.57 47.46 180 top
C3724  0.1uF  [CAP0201_0-5]  24.69 82.9 90 bottom
C3725  0.1uF  [CAP0201_0-5]  24.61 84.26 270 bottom
C3726  0.1uF  [CAP0201_0-5]  35.48 104.86 180 bottom
C3727  0.1uF  [CAP0201_0-5]  35.06 108.9 270 bottom
C3728  0.1uF  [CAP0201_0-5]  34.34 121.54 270 top
C3729  0.1uF  [CAP0201_0-5]  20.74 102.12 90 top
C3730  0.1uF  [CAP0201_0-5]  17.59 102.22 0 top
C3731  0.1uF  [CAP0201_0-5]  17.75 51.28 90 top
C3732  0.1uF  [CAP0402_0-75]  79.04 97.17 90 top
C3733  0.1uF  [CAP0402_0-75]  44.6 128.09 270 top
C3738  2.2uF  [CAP0603_1]  35.81 57.26 0 top
C3740  0.1uF  [CAP0201_0-5]  55.81 122.03 180 top
C3741  0.1uF  [CAP0201_0-5]  55.58 129.57 90 top
C3742  4.7uF  [CAP0402_0-75]  63.48 74.09 0 bottom
C3743  0.1uF  [CAP0201_0-5]  63.53 75.13 180 bottom
C3744  4.7uF  [CAP0402_0-75]  123.37 66.52 180 top
C3745  0.1uF  [CAP0201_0-5]  123.55 65.33 0 top
C3746  0.1uF  [CAP0201_0-5]  10.47 68.1 180 top
C3747  1uF  [CAP0201_0-5]  10.13 63.78 0 top
C3750  22pF  [CAP0201_0-5]  24.92 53.88 90 top
C3751  1uF  [CAP0201_0-5]  62.37 81.39 270 bottom
C3752  1uF  [CAP0201_0-5]  65.79 83.66 90 bottom
C3753  2.2uF  [CAP0603_1]  75.9 91.68 0 bottom
C3754  2.2uF  [CAP0603_1]  40.98 97.47 90 bottom
C3755  10uF  [CAP0603_1]  40.93 97.52 90 top
C3756  4.7uF  [CAP0603_1]  41.87 92.43 180 bottom
C3757  10uF  [CAP0603_1]  75.9 93.69 0 bottom
C3758  0.1uF  [CAP0201_0-5]  64.76 82.88 270 bottom
C3759  0.1uF  [CAP0201_0-5]  61.72 85.14 180 bottom
C3760  2.2uF  [CAP0603_1]  41.24 69.44 180 top
C3761  0.1uF  [CAP0402_0-75]  48.77 68.96 180 bottom
C3762  0.1uF  [CAP0402_0-75]  45.54 68.94 90 bottom
C3763  0.1uF  [CAP0402_0-75]  34.78 76.96 180 bottom
C3764  0.1uF  [CAP0402_0-75]  31.55 77.17 90 bottom
C3767  0.1uF  [CAP0201_0-5]  66.51 84.46 225 bottom
C3768  0.1uF  [CAP0201_0-5]  95.38 59.77 0 top
C3769  0.1uF  [CAP0201_0-5]  95.4 56.44 0 top
C3771  0.1uF  [CAP0201_0-5]  104.3 60.5 180 top
C3772  1uF  [CAP0201_0-5]  104.3 61.52 180 top
C3773  0.1uF  [CAP0201_0-5]  51.96 51.26 180 top
C3774  0.1uF  [CAP0201_0-5]  50.87 54.65 90 top
C3775  0.1uF  [CAP0201_0-5]  59.05 24.51 0 bottom
C3779  0.1uF  [CAP0201_0-5]  53.7 69.27 90 bottom
C3780  0.1uF  [CAP0201_0-5]  50.22 68.86 270 bottom
C3781  0.1uF  [CAP0402_0-75]  52.02 66.07 180 bottom
D1  TPD1E10B06DPYR  [DIO_DFN0402_0-5]  7.82 52.69 270 top
D2  PLVA650A  [DIO_SOT23_123]  15.78 55.36 0 top
D3  TPD1E10B06DPYR  [DIO_DFN0402_0-5]  53.62 8.73 270 top
D5  BAT54CWT1G  [DIO_SOT323-3_1-1]  25.38 18.31 90 top
D6  BZX84C6V8LT1G  [SOT23-123_1-2]  45.75 12.06 90 top
D7  TPD1E01B04DPLT  [DIO_DFN0201_0-4]  23.45 10.52 0 top
D8  TPD1E01B04DPLT  [DIO_DFN0201_0-4]  37.86 9.77 90 top
D9  ESD122DMXR  [X2SON3_ESD122DMX_30X40_0-4]  39.39 9.53 270 top
D11  TPD1E10B06DPYR  [DIO_DFN0402_0-5]  21.55 106.77 180 top
D12  TPD1E10B06DPYR  [DIO_DFN0402_0-5]  49.75 113.69 180 top
D13  TPD1E10B06DPYR  [DIO_DFN0402_0-5]  36.09 41.47 270 bottom
D14  TPD1E10B06DPYR  [DIO_DFN0402_0-5]  92.68 94.81 90 bottom
D16  TPD1E01B04DPLT  [DIO_DFN0201_0-4]  41.69 5.07 90 bottom
D17  TPD1E01B04DPLT  [DIO_DFN0201_0-4]  24.54 4.79 180 bottom
D18  TPD1E10B06DPYR  [DIO_DFN0402_0-5]  54.06 129.57 90 top
FL1  120E  [EMIFIL_BLM18P_0603_0-8]  87.93 159.26 0 top
FL2  120E  [EMIFIL_BLM18P_0603_0-8]  49.64 153.61 180 top
FL4  120E  [EMIFIL_BLM15A_0402_0-6]  112.27 73.68 90 top
FL6  120E  [EMIFIL_BLM15A_0402_0-6]  67.87 74.93 180 bottom
FL8  26E  [EMIFIL_BLM18K_0603]  74.41 97.26 180 top
FL9  120E  [EMIFIL_BLM15A_0402_0-6]  58.06 79.04 90 bottom
FL10  120E  [EMIFIL_BLM15A_0402_0-6]  63.77 54.92 0 bottom
FL13  120E  [EMIFIL_BLM15A_0402_0-6]  78.18 71.58 180 bottom
FL17  120E  [EMIFIL_BLM15A_0402_0-6]  48.75 29.56 180 bottom
FL18  120E  [EMIFIL_BLM15A_0402_0-6]  51.94 21.97 270 bottom
FL19  120E  [EMIFIL_BLM15A_0402_0-6]  71.68 85.37 270 bottom
FL20  120E  [EMIFIL_BLM15A_0402_0-6]  63.5 67 180 bottom
FL21  120E  [EMIFIL_BLM15A_0402_0-6]  70.92 73.9 180 bottom
FL22  120E  [EMIFIL_BLM15A_0402_0-6]  65.74 67.46 90 bottom
FL23  120E  [EMIFIL_BLM15A_0402_0-6]  104.48 62.79 0 top
J1  CON_AUDIOJACK6_STX-4235  [CON_AV6_STX-4235-3-3_S_R_T_26]  39.89 173.5 180 top
J2  CON_AUDIOJACK6_STX-4235  [CON_AV6_STX-4235-3-3_S_R_T_26]  57.03 173.5 180 top
J3  CON_AUDIOJACK6_STX-4235  [CON_AV6_STX-4235-3-3_S_R_T_26]  74.18 173.5 180 top
J4  CON_AUDIOJACK6_STX-4235  [CON_AV6_STX-4235-3-3_S_R_T_26]  91.58 173.5 180 top
J7  HDR_1X2  [HDR_1X2_90120-0122_S_T_5-6]  54.75 157.68 0 top
J9  HDR_1X3  [HDR_1X3_100_S_T]  21.61 160.86 90 top
J10  HDR_1X2  [HDR_1X2_90120-0122_S_T_5-6]  73.64 143.51 270 top
J12  RECP_40X2  [CON_40X2_QSE-040-01_S_S_S]  117.18 131.58 270 top
J13  RECP_40X2  [CON_40X2_QSE-040-01_S_S_S]  10.15 134.84 90 top
J14  HDR_2X10  [HDR_2X10_FTR-110-51-D-06_S_S_8-7]  31.36 108.57 180 top
J16  HDR_1X2  [HDR_1X2_61300211121_S_T_8-6]  13.64 41.14 90 top
J17  CON_MUSB-B_5_F  [CON_MUSBB5_629105150521_S_R_S_2-7]  2.7 50.01 270 top
J18  CON_BTOB_2X24_M  [CON_BTOB2X24_DF40GB-48DP_P_S_S_1-3]  77.81 40.98 0 top
J19  CON_BTOB_2X24_M  [CON_BTOB2X24_DF40GB-48DP_P_S_S_1-3]  110.24 40.98 0 top
J21  HDR_2X5  [HDR_2X5_PEC05DAAN_S_T_8-6]  21.21 30.4 90 top
J22  CON_MUSB-B_5_F  [CON_MUSBB5_629105150521_S_R_S_2-7]  56.15 2.7 0 top
J24  CON_USB-C_24_F  [CON_USBC24_2012670_S_R_S_3-9]  24.39 3.88 0 top
J25  CON_USB-C_24_F  [CON_USBC24_2012670_S_R_S_3-9]  39.39 3.88 0 top
J26  CON_SDCARD9_MEM2052-00-195-00-A  [CON_SD9_MEM2052-00-195-00_S_R_S_2]  119 74.57 270 bottom
J28  HDR_2X4  [HDR_2X4_90131-07_S_T_9-5]  94.74 124.66 0 top
J29  HDR_1X3  [HDR_1X3_87224-3_S_T_10-8]  104.88 120.27 90 top
J31  HDR_6X2  [HDR_6X2_61301221121_P_S_T_8-6]  121.29 63.21 270 top
J32  HDR_1X2  [HDR_1X2_61300211121_S_T_8-6]  91.26 92.22 90 top
J33  HDR_1X2  [HDR_1X2_61300211121_S_T_8-6]  42.54 124.32 0 top
J34  HDR_1X2  [HDR_1X2_61300211121_S_T_8-6]  23.61 168.59 180 top
L2  2.2uH  [IND0806]  44.49 153.86 180 top
L3  2.2uH  [IND0806]  55.27 143.96 0 top
L4  0.22uH  [IND1210_1-2]  27.91 63.02 90 top
L5  0.22uH  [IND1210_1-2]  31.73 63.02 90 top
L6  0.22uH  [IND1210_1-2]  27.91 49.58 270 top
L7  0.22uH  [IND1210_1-2]  31.73 49.58 270 top
L10  90E  [IND4_DLW21H_90X60_SMD_1-4]  39.39 12.17 270 top
L11  0.47uH  [IND0806_1-2]  84.61 32.43 90 bottom
L24  6.8uH  [IND_XAL8080_330X350_SMD_8]  9.53 24.99 90 top
LD1  150080VS75000  [LED_150080VS75000_80X50_SMD_0-8]  65.14 132.2 90 top
LD2  150080VS75000  [LED_150080VS75000_80X50_SMD_0-8]  36.53 68.05 180 top
LD3  150040RS73220  [LED_150040GS73220_40X20_SMD_0-4]  37.03 79.41 90 top
LD4  150040VS73220  [LED_150040GS73220_40X20_SMD_0-4]  50.44 48.42 180 top
LD5  150080VS75000  [LED_150080VS75000_80X50_SMD_0-8]  31.97 77 0 top
LD6  150080VS75000  [LED_150080VS75000_80X50_SMD_0-8]  43.51 118.24 180 top
LD7  150080VS75000  [LED_150080VS75000_80X50_SMD_0-8]  42.46 31.75 90 top
LD9  150080VS75000  [LED_150080VS75000_80X50_SMD_0-8]  37.07 12.94 270 top
LD10  150080VS75000  [LED_150080VS75000_80X50_SMD_0-8]  62.11 128.76 270 top
LD13  150080VS75000  [LED_150080VS75000_80X50_SMD_0-8#2]  22.33 14.88 180 top
LD14  150040RS73220  [LED_150040GS73220_40X20_SMD_0-4]  25.43 38.03 90 top
NOREF  -  [unnamed]  128 5.08 90 top
NOREF#2  -  [unnamed#2]  3.69 164.38 0 top
NOREF#3  -  [#3]  0.7 -33.17 0 top
NOREF#4  -  [unnamed#2]  118.25 8.82 45 top
NOREF#5  -  [unnamed#2]  66.74 40.35 270 top
NOREF#6  -  [unnamed#2]  -6.06 4 270 top
NOREF#7  -  [unnamed#2]  3.81 3.81 90 top
NOREF#8  -  [unnamed#2]  123.17 3.9 270 top
NOREF#9  -  [unnamed#2]  3.69 8.75 0 top
NOREF#10  -  [unnamed]  -1 171.92 270 top
NOREF#11  -  [unnamed#2]  -6.06 9.33 180 top
NOREF#12  -  [unnamed#2]  123.39 164.38 0 top
NOREF#13  -  [unnamed#2]  133 9.4 180 top
NOREF#14  -  [unnamed#2]  123.19 173.19 270 top
NOREF#15  -  [unnamed#2]  10.16 161.83 180 top
NOREF#16  -  [unnamed#2]  117.17 104.59 0 top
NOREF#17  -  [unnamed]  128 92.45 90 top
NOREF#18  -  [unnamed#2]  99.17 40.35 270 top
NOREF#19  -  [unnamed#2]  3.81 173.19 90 top
NOREF#20  -  [unnamed]  -1 5.08 270 top
NOREF#21  -  [unnamed]  -1 92.45 270 top
NOREF#22  -  [unnamed]  128 171.92 90 top
NOREF#23  -  [unnamed#2]  117.17 158.58 180 top
NOREF#24  -  [unnamed#2]  10.16 107.84 0 top
NOREF#25  -  [#3]  0 177 0 top
NOREF#26  -  [#3]  -10 177 0 top
NOREF#27  -  [unnamed]  -1 36.63 270 top
NOREF#28  -  [unnamed#2]  -6 172.94 0 top
NOREF#29  -  [unnamed#2]  90.74 3.9 270 top
NOREF#30  -  [#3]  -477.3 -5.8 0 top
NOREF#31  -  [unnamed#2]  90.87 40.35 270 top
NOREF#32  -  [#3]  0 0 90 top
NOREF#33  -  [#3]  -421.56 195.14 0 top
NOREF#34  -  [unnamed#2]  133.06 167.67 0 top
NOREF#35  -  [#3]  -57.87 -32.89 0 top
NOREF#36  -  [unnamed]  -1 140.37 270 top
NOREF#37  -  [unnamed]  128 140.37 90 top
NOREF#38  -  [unnamed#2]  -6 167.6 0 top
NOREF#39  -  [unnamed#2]  123.3 40.35 270 top
NOREF#40  -  [unnamed]  128 36.63 90 top
NOREF#41  -  [#3]  -419.39 -163.3 0 top
NOREF#42  -  [unnamed#2]  133.06 173 90 top
NOREF#43  -  [unnamed#2]  133 4.06 180 top
NOREF#44  -  [unnamed#2]  133.06 167.67 0 bottom
NOREF#45  -  [unnamed#2]  123.39 164.38 180 bottom
NOREF#46  -  [unnamed#2]  -6.06 9.33 180 bottom
NOREF#47  -  [unnamed#2]  -6 167.6 180 bottom
NOREF#48  -  [unnamed#2]  3.69 164.38 180 bottom
NOREF#49  -  [unnamed#2]  133 9.4 0 bottom
Q1  CSD16301Q2  [WSON6_CSD13202Q2_80X80_0-8]  67.82 132.13 90 top
Q2  ABC817-40-HF  [SOT23-123_1-2]  39.77 70.41 90 bottom
Q3  BSS138LT1G  [SOT23-123_1-2]  53.36 48.42 180 top
Q4  BSS138LT1G  [SOT23-123_1-2]  14.96 59.04 0 top
Q5  CSD16301Q2  [WSON6_CSD13202Q2_80X80_0-8]  61.91 132.52 270 top
Q7  IRLML6401  [TO_SOT23-123]  18.56 107.7 90 top
Q8  CSD25310Q2  [SON6_CSD17313Q2_80X80]  45.37 17.12 0 bottom
Q9  CSD25310Q2  [SON6_CSD17313Q2_80X80]  42.67 17.12 180 bottom
Q10  CSD16301Q2  [WSON6_CSD13202Q2_80X80_0-8]  37.63 16.26 0 bottom
Q12  IRLML6401  [TO_SOT23-123]  57.02 117.96 270 top
R3  4.3K  [RES0402_0-5]  41.97 163.39 270 top
R4  4.3K  [RES0402_0-5]  43.24 163.39 270 top
R5  4.3K  [RES0402_0-5]  45.81 163.39 270 top
R6  4.3K  [RES0402_0-5]  47.08 163.39 270 top
R7  4.3K  [RES0402_0-5]  59.11 163.39 270 top
R8  4.3K  [RES0402_0-5]  60.38 163.39 270 top
R9  4.3K  [RES0402_0-5]  62.95 163.39 270 top
R10  4.3K  [RES0402_0-5]  64.22 163.39 270 top
R17  10K  [RES0201_0-5]  116.65 66.8 270 top
R18  10K  [RES0201_0-5]  119.09 68.35 270 top
R20  10K  [RES0201_0-5]  52.31 153.84 270 top
R21  0E  [RES0201_0-5]  118.16 69.62 180 top
R22  10K  [RES0201_0-5]  53.55 153.54 90 top
R23  10K  [RES0201_0-5]  54.44 153.54 270 top
R24  0E  [RES0201_0-5]  71.43 152.82 180 top
R25  0E  [RES0201_0-5]  88.82 152.82 180 top
R26  10K  [RES0201_0-5]  51.69 152.6 180 top
R27  10K  [RES0201_0-5]  97.64 150.88 180 top
R28  4.7K  [RES0201_0-5]  98.96 150.88 0 top
R29  10K  [RES0201_0-5]  78.81 150.53 180 top
R30  10K  [RES0201_0-5]  96.23 150.21 90 top
R31  10K  [RES0201_0-5]  77.5 149.99 0 top
R32  10K  [RES0201_0-5]  94.9 149.99 0 top
R33  10K  [RES0201_0-5]  80.82 149.93 0 top
R34  0E  [RES0201_0-5]  49.68 150.98 270 top
R35  22K  [RES0402_0-5]  97.59 149.66 0 top
R36  4.7K  [RES0201_0-5]  82.04 149.65 90 top
R37  0E  [RES0201_0-5]  78.53 149.36 90 top
R38  0E  [RES0402_0-5]  51.02 149.2 0 top
R46  0E  [RES0201_0-5]  48.63 148.01 180 top
R54  47K_1%  [RES0201_0-5]  119.85 74.95 0 top
R55  47K_1%  [RES0201_0-5]  115.35 75.45 180 top
R56  4.7K  [RES0201_0-5]  104.21 147.56 180 top
R57  47K_1%  [RES0201_0-5]  119.85 75.89 0 top
R58  4.7K  [RES0201_0-5]  98.51 147.17 0 top
R60  10K  [RES0201_0-5]  45.32 144.27 90 top
R61  10K  [RES0201_0-5]  46.21 144.27 270 top
R62  10K  [RES0201_0-5]  47.1 144.27 90 top
R63  10K  [RES0201_0-5]  47.99 144.27 270 top
R64  47K_1%  [RES0201_0-5]  115.36 76.4 180 top
R65  47K_1%  [RES0201_0-5]  119.85 76.83 0 top
R66  47K_1%  [RES0201_0-5]  115.35 77.33 180 top
R67  0E  [RES0603_0-75]  62.28 142.48 180 top
R68  10K  [RES0402_0-5]  66.5 142.38 270 top
R69  10K  [RES0402_0-5]  104.76 144.9 180 top
R70  10K  [RES0201_0-5]  111.54 78.41 90 top
R73  0E  [RES0201_0-5]  75.2 59.61 180 top
R74  0E  [RES0201_0-5]  75.21 58.64 180 top
R75  4.7K  [RES0201_0-5]  75.22 56.88 0 top
R76  4.7K  [RES0201_0-5]  75.22 57.64 180 top
R78  10K  [RES0402_0-5]  63.84 139.32 270 top
R81  33E  [RES0402_0-5]  28.47 162.61 270 top
R82  0E  [RES0402_0-5]  47.2 80.62 270 top
R83  4.7K  [RES0201_0-5]  77.26 62.18 270 top
R84  0E  [RES0201_0-5]  68.99 137.9 180 top
R85  4.7K  [RES0201_0-5]  78.21 62.18 90 top
R88  59E_1%  [RES0402_0-5]  24.16 157.29 90 top
R89  0E  [RES0201_0-5]  79.2 61.34 270 top
R90  10K  [RES0402_0-5]  67.14 136.21 180 top
R93  59E_1%  [RES0402_0-5]  24.16 159.32 90 top
R94  10K  [RES0201_0-5]  58.39 137.57 90 top
R97  0E  [RES0603_0-75]  83.94 59.41 0 top
R98  10K  [RES0201_0-5]  54.56 138.88 180 top
R102  0E  [RES0402_0-5]  27.54 155.46 0 top
R107  10K  [RES0201_0-5]  89.78 135.54 180 top
R108  0E  [RES0201_0-5]  95.61 136.2 270 top
R112  10K  [RES0201_0-5]  72.48 140.34 0 top
R115  10K  [RES0201_0-5]  99.94 96.9 0 top
R116  0E  [RES0201_0-5]  99.94 95.89 0 top
R117  10K  [RES0201_0-5]  105.16 94.27 270 top
R118  4.7K  [RES0201_0-5]  40.93 103.39 90 top
R119  4.7K  [RES0201_0-5]  42.2 103.39 90 top
R121  0E  [RES0201_0-5]  61.36 125.93 180 top
R122  10K  [RES0201_0-5]  60.15 126.21 90 top
R123  10K  [RES0201_0-5]  52.58 109.11 90 top
R124  10K  [RES0201_0-5]  55.25 128.12 90 top
R125  0E  [RES0201_0-5]  52.58 107.02 270 top
R126  1K  [RES0201_0-5]  77.05 128.22 90 top
R127  1K  [RES0201_0-5]  78.32 128.22 90 top
R128  1K  [RES0201_0-5]  79.59 128.22 90 top
R129  1K  [RES0201_0-5]  80.86 128.22 90 top
R130  1K  [RES0201_0-5]  82.13 128.22 90 top
R131  1K  [RES0201_0-5]  83.4 128.22 90 top
R132  1K  [RES0201_0-5]  84.67 128.22 90 top
R133  1K  [RES0201_0-5]  85.94 128.22 90 top
R134  1K  [RES0201_0-5]  64.54 128.22 90 top
R135  1K  [RES0201_0-5]  65.81 128.22 90 top
R136  1K  [RES0201_0-5]  67.08 128.22 90 top
R137  1K  [RES0201_0-5]  68.35 128.22 90 top
R138  1K  [RES0201_0-5]  69.62 128.22 90 top
R139  1K  [RES0201_0-5]  70.89 128.22 90 top
R140  1K  [RES0201_0-5]  72.16 128.22 90 top
R141  1K  [RES0201_0-5]  73.43 128.22 90 top
R143  10K  [RES0201_0-5]  90.35 60.53 180 top
R145  100K  [RES0201_0-5]  77.05 116.79 270 top
R146  100K  [RES0201_0-5]  78.32 116.79 270 top
R147  100K  [RES0201_0-5]  79.59 116.79 270 top
R148  100K  [RES0201_0-5]  80.86 116.79 270 top
R149  100K  [RES0201_0-5]  82.13 116.79 270 top
R150  100K  [RES0201_0-5]  83.4 116.79 270 top
R151  100K  [RES0201_0-5]  84.67 116.79 270 top
R152  100K  [RES0201_0-5]  85.94 116.79 270 top
R153  100K  [RES0201_0-5]  64.54 116.79 270 top
R154  100K  [RES0201_0-5]  65.81 116.79 270 top
R155  100K  [RES0201_0-5]  67.08 116.79 270 top
R156  100K  [RES0201_0-5]  68.35 116.79 270 top
R157  100K  [RES0201_0-5]  69.62 116.79 270 top
R158  100K  [RES0201_0-5]  70.89 116.79 270 top
R159  100K  [RES0201_0-5]  72.16 116.79 270 top
R160  100K  [RES0201_0-5]  73.43 116.79 270 top
R166  10K  [RES0201_0-5]  85.45 63.27 90 top
R170  0E  [RES0603_0-75]  70.08 72.67 90 top
R176  0E  [RES0402_0-5]  72.43 100.29 90 bottom
R177  0E  [RES0402_0-5]  71.83 98.28 90 bottom
R178  22E  [RES0402_0-5]  66.58 97.45 270 top
R179  22E  [RES0402_0-5]  69.07 97.45 270 top
R180  220E  [RES0402_0-5]  65.06 134.78 180 top
R190  0E  [RES0402_0-5]  61.16 97.19 90 bottom
R191  0E  [RES0402_0-5]  69.94 100.29 90 bottom
R195  470E  [RES0402_0-5]  24.22 38.04 90 top
R197  0E  [RES0402_0-5]  55.96 95.57 270 top
R202  10K  [RES0201_0-5]  118.75 74.07 180 top
R203  10K  [RES0201_0-5]  69.68 131.44 270 top
R205  0E  [RES0201_0-5]  74.41 76.07 0 bottom
R206  0E  [RES0402_0-5]  54.62 95.54 270 top
R210  62E_1%  [RES0402_0-5]  66.7 65.86 270 top
R211  10K  [RES0201_0-5]  17.59 103.48 0 top
R212  10K  [RES0201_0-5]  17.59 104.24 0 top
R213  0E  [RES0402_0-5]  67.98 130.05 0 top
R214  1K  [RES0201_0-5]  36.3 100.18 90 top
R216  22E  [RES0201_0-5]  67.75 69.24 90 top
R217  1K  [RES0201_0-5]  36.31 102.01 270 top
R218  4.87K_1%  [RES0402_0-5]  23.79 100.26 90 top
R219  0E  [RES0201_0-5]  3.05 83.08 90 top
R220  10K  [RES0201_0-5]  21.64 104.47 180 top
R221  0E  [RES0201_0-5]  3.45 92.58 270 top
R224  0E  [RES0201_0-5]  3.94 83.08 90 top
R225  10K  [RES0201_0-5]  22.03 103.49 270 top
R227  0E  [RES0201_0-5]  4.34 92.58 270 top
R228  0E  [RES0201_0-5]  75.6 89.25 0 top
R229  1K_1%  [RES0402_0-5]  19.92 98.17 270 top
R230  1K_1%  [RES0402_0-5]  21.19 98.17 270 top
R231  1K_1%  [RES0402_0-5]  22.46 98.17 270 top
R232  1K_1%  [RES0402_0-5]  23.73 98.17 270 top
R233  0E  [RES0201_0-5]  4.83 83.08 90 top
R234  62E_1%  [RES0402_0-5]  76.03 77.75 0 bottom
R235  0E  [RES0201_0-5]  5.23 92.58 270 top
R236  4.7K  [RES0201_0-5]  29.53 97.29 270 top
R237  4.7K  [RES0201_0-5]  30.3 97.29 270 top
R238  4.7K  [RES0201_0-5]  87.01 93.14 90 top
R239  0E  [RES0201_0-5]  75.21 86.46 270 top
R240  10K  [RES0201_0-5]  38.82 83.56 270 top
R241  4.7K  [RES0201_0-5]  36.48 95.74 90 top
R242  10K  [RES0201_0-5]  85.6 91.78 0 top
R243  0E  [RES0402_0-5]  35.72 56.95 0 bottom
R246  49.9E_1%  [RES0402_0-5]  16.29 93.64 180 top
R249  0E  [RES0201_0-5]  53.75 76.49 270 top
R252  0E  [RES0201_0-5]  53.47 76.21 0 top
R253  0E  [RES0201_0-5]  53.47 75.13 0 top
R254  0E  [RES0201_0-5]  53.75 74.85 90 top
R255  100K_1%  [RES0402_0-5]  40.32 77.5 180 top
R256  62E_1%  [RES0402_0-5]  44.63 84.87 0 top
R258  182K_1%  [RES0402_0-5]  38.82 77.01 270 top
R259  4.7K  [RES0201_0-5]  44.14 83.62 90 top
R260  220E  [RES0402_0-5]  37.11 70.46 90 bottom
R261  0E  [RES0201_0-5]  51.07 75.99 270 bottom
R262  47K_1%  [RES0201_0-5]  89.51 76.15 0 top
R263  47K_1%  [RES0201_0-5]  89.3 75.37 0 top
R264  47K_1%  [RES0201_0-5]  89.3 74.22 0 top
R265  0.001E_1%  [RES_CST0612_0612-4_0-9]  27.38 68.33 270 top
R266  47K_1%  [RES0201_0-5]  89.3 73.08 0 top
R267  47K_1%  [RES0201_0-5]  89.3 71.94 0 top
R268  10K  [RES0201_0-5]  43.36 75.11 90 top
R269  47K_1%  [RES0201_0-5]  89.3 70.79 0 top
R270  47K_1%  [RES0201_0-5]  89.3 69.65 0 top
R271  0E  [RES0201_0-5]  17.65 82.3 180 top
R272  1K  [RES0402_0-5]  41.74 71.78 180 bottom
R275  47K_1%  [RES0201_0-5]  89.3 68.51 0 top
R276  220E  [RES0402_0-5]  37.03 81.52 270 top
R277  1K  [RES0402_0-5]  11.06 80.97 180 top
R278  10K  [RES0201_0-5]  12.77 80.96 180 top
R280  10K  [RES0201_0-5]  11.36 78.88 0 top
R281  0E  [RES0201_0-5]  37.89 62.52 270 top
R282  10K  [RES0201_0-5]  38.68 62.52 270 top
R283  0E  [RES0201_0-5]  14.9 79.17 180 top
R284  62E_1%  [RES0402_0-5]  52.19 88.23 270 top
R285  10K  [RES0201_0-5]  14.9 78.23 0 top
R286  0E  [RES0201_0-5]  55.78 47.19 90 top
R287  220E  [RES0402_0-5]  34.36 78.01 270 top
R288  10K  [RES0201_0-5]  40.03 61.12 0 top
R289  20K_1%  [RES0402_0-5]  36.04 77.63 0 top
R290  0E  [RES0201_0-5]  38.04 60.83 270 top
R291  10K  [RES0201_0-5]  38.83 60.83 270 top
